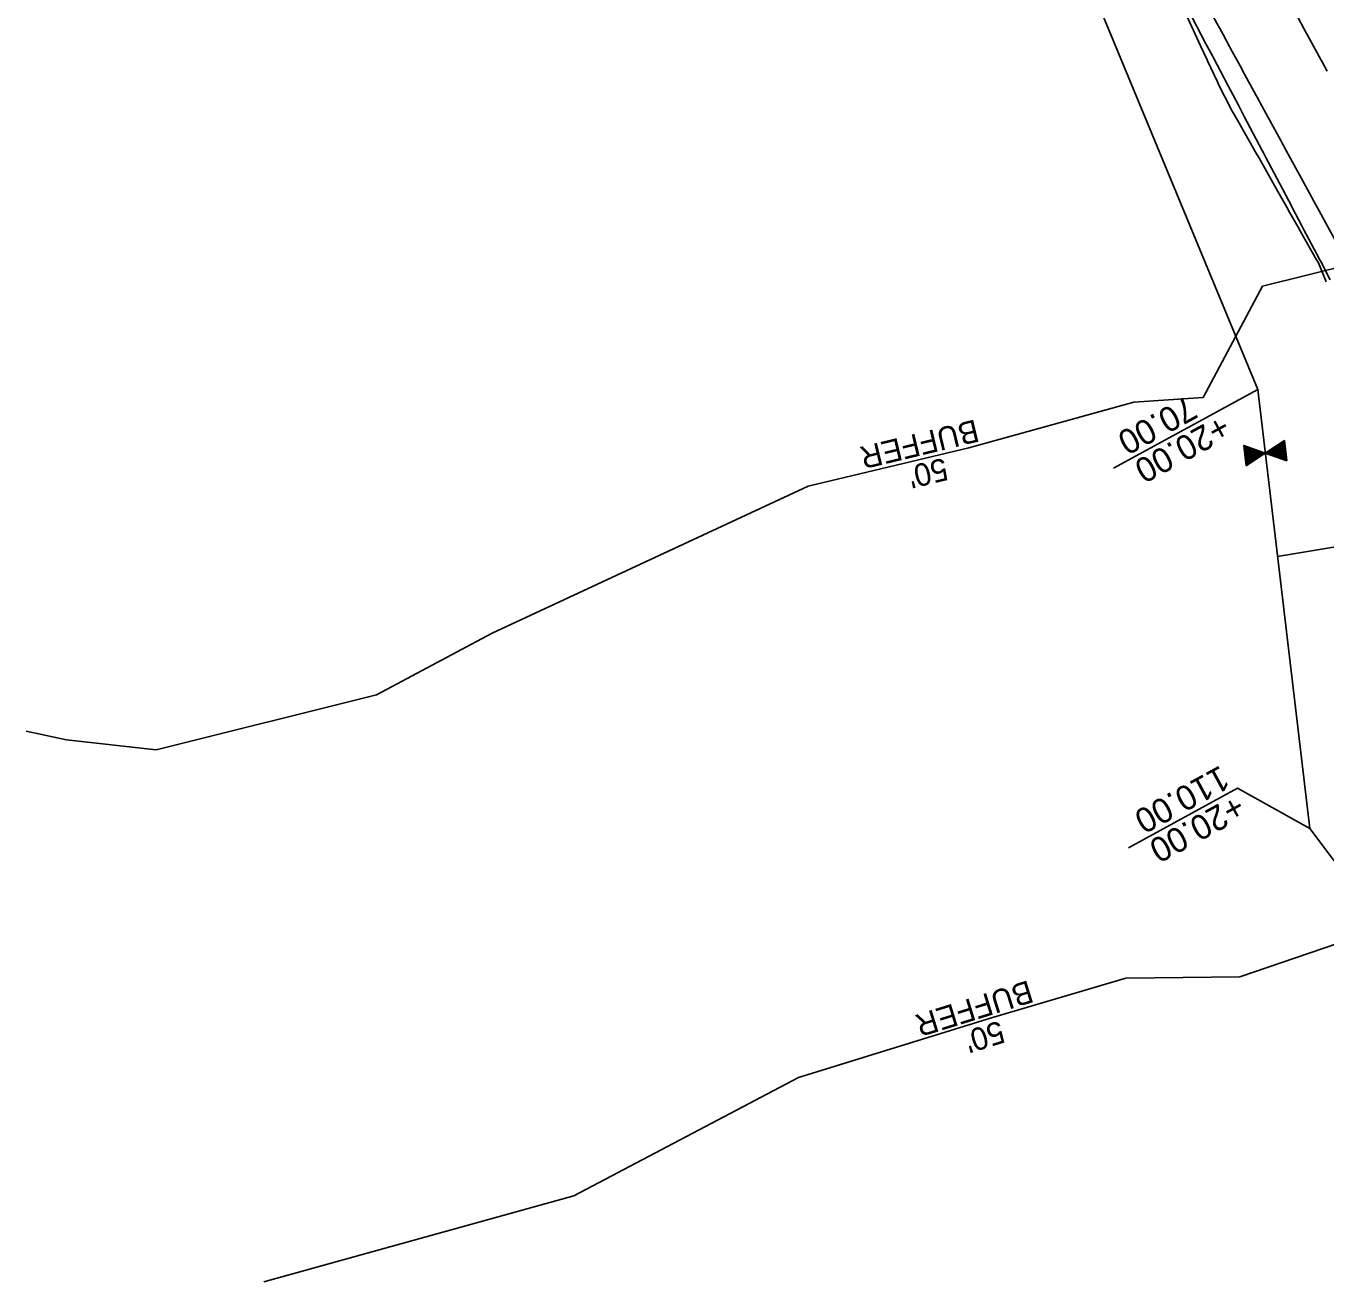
# Model space of a CAD drawing. Extents: x 1627557 to 1636561, y 783843 to 794002.
# Drawn here: x 1627658.9 to 1627975.8, y 784734.6 to 785040.7 of the extents above; entities that cross this region are included whole.
import ezdxf

# ---------------------------------------------------------------- set-up
doc = ezdxf.new("R2010")
doc.units = 0
for name, color, linetype in [('25 FT Buffer', 7, 'Continuous'), ('GATE', 7, 'Continuous'), ('R_Clearzone', 7, 'Continuous'), ('R_Ditch', 7, 'Continuous'), ('R_Proposed Const Limits', 7, 'Continuous'), ('R_Proposed Shoulder', 7, 'Continuous'), ('R_ROW', 7, 'Continuous'), ('R_ROW Annot', 7, 'Continuous')]:
    doc.layers.add(name, color=color, linetype=linetype)

msp = doc.modelspace()

# ---------------------------------------------------------------- linework, layer by layer
at = {"layer": '25 FT Buffer'}
for points in [[(1628054.55, 785023.15), (1628004.24, 784988.22), (1627960.38, 784977.27), (1627945.89, 784950.14), (1627929.03, 784949.04), (1627888.77, 784937.95), (1627849.63, 784928.54), (1627772.56, 784892.79), (1627744.38, 784877.73), (1627690.67, 784864.34), (1627668.83, 784866.74), (1627658.94, 784868.89)], [(1628128.73, 784912.02), (1628047.84, 784832.47), (1628028.94, 784828.64), (1627988.66, 784820.54), (1627954.84, 784809.03), (1627927.06, 784808.64), (1627894.29, 784799.05), (1627847.27, 784784.48), (1627792.52, 784755.67), (1627716.91, 784734.64)]]:
    msp.add_lwpolyline(points, dxfattribs=at)
at = {"layer": 'GATE'}
for p, q in [((1627965.69, 784934.93), (1627965.16, 784939.33)), ((1627965.79, 784934.89), (1627965.26, 784939.39)), ((1627965.9, 784934.86), (1627965.35, 784939.45)), ((1627966, 784934.82), (1627965.44, 784939.51)), ((1627966.11, 784934.78), (1627965.54, 784939.57)), ((1627966.21, 784934.74), (1627965.63, 784939.64)), ((1627956.37, 784933.54), (1627955.78, 784938.49)), ((1627956.47, 784933.6), (1627955.89, 784938.45)), ((1627956.56, 784933.66), (1627955.99, 784938.41)), ((1627956.65, 784933.72), (1627956.1, 784938.38)), ((1627956.75, 784933.79), (1627956.2, 784938.34)), ((1627956.84, 784933.85), (1627956.31, 784938.3)), ((1627956.93, 784933.91), (1627956.41, 784938.26)), ((1627957.03, 784933.97), (1627956.52, 784938.23)), ((1627957.12, 784934.03), (1627956.62, 784938.19)), ((1627957.21, 784934.09), (1627956.73, 784938.15)), ((1627957.31, 784934.15), (1627956.83, 784938.11)), ((1627957.4, 784934.22), (1627956.94, 784938.07)), ((1627957.49, 784934.28), (1627957.04, 784938.04)), ((1627957.59, 784934.34), (1627957.15, 784938)), ((1627957.68, 784934.4), (1627957.25, 784937.96)), ((1627957.77, 784934.46), (1627957.36, 784937.92)), ((1627957.87, 784934.52), (1627957.47, 784937.89)), ((1627957.96, 784934.58), (1627957.57, 784937.85)), ((1627958.05, 784934.65), (1627957.68, 784937.81)), ((1627958.15, 784934.71), (1627957.78, 784937.77)), ((1627958.24, 784934.77), (1627957.89, 784937.73)), ((1627958.33, 784934.83), (1627957.99, 784937.7)), ((1627958.43, 784934.89), (1627958.1, 784937.66)), ((1627958.52, 784934.95), (1627958.2, 784937.62)), ((1627958.61, 784935.01), (1627958.31, 784937.58)), ((1627958.71, 784935.08), (1627958.41, 784937.54)), ((1627958.8, 784935.14), (1627958.52, 784937.51)), ((1627958.89, 784935.2), (1627958.62, 784937.47)), ((1627958.99, 784935.26), (1627958.73, 784937.43)), ((1627959.08, 784935.32), (1627958.83, 784937.39)), ((1627959.17, 784935.38), (1627958.94, 784937.36)), ((1627959.27, 784935.45), (1627959.04, 784937.32)), ((1627959.36, 784935.51), (1627959.15, 784937.28)), ((1627959.45, 784935.57), (1627959.25, 784937.24)), ((1627959.55, 784935.63), (1627959.36, 784937.2)), ((1627959.64, 784935.69), (1627959.46, 784937.17)), ((1627959.73, 784935.75), (1627959.57, 784937.13)), ((1627959.83, 784935.81), (1627959.67, 784937.09)), ((1627959.92, 784935.88), (1627959.78, 784937.05)), ((1627960.01, 784935.94), (1627959.89, 784937.02)), ((1627960.11, 784936), (1627959.99, 784936.98)), ((1627960.2, 784936.06), (1627960.1, 784936.94)), ((1627960.29, 784936.12), (1627960.2, 784936.9)), ((1627960.39, 784936.18), (1627960.31, 784936.86)), ((1627960.48, 784936.24), (1627960.41, 784936.83)), ((1627960.57, 784936.31), (1627960.52, 784936.79)), ((1627960.67, 784936.37), (1627960.62, 784936.75)), ((1627960.76, 784936.43), (1627960.73, 784936.71)), ((1627960.85, 784936.49), (1627960.83, 784936.68)), ((1627960.95, 784936.55), (1627960.94, 784936.64)), ((1627961.06, 784936.59), (1627961.05, 784936.62)), ((1627961.16, 784936.56), (1627961.15, 784936.68)), ((1627961.27, 784936.52), (1627961.24, 784936.75)), ((1627961.37, 784936.48), (1627961.33, 784936.81)), ((1627961.48, 784936.44), (1627961.43, 784936.87)), ((1627961.58, 784936.41), (1627961.52, 784936.93)), ((1627961.69, 784936.37), (1627961.61, 784936.99)), ((1627961.79, 784936.33), (1627961.71, 784937.05)), ((1627961.9, 784936.29), (1627961.8, 784937.11)), ((1627962, 784936.25), (1627961.89, 784937.18)), ((1627962.11, 784936.22), (1627961.99, 784937.24)), ((1627962.22, 784936.18), (1627962.08, 784937.3)), ((1627962.32, 784936.14), (1627962.18, 784937.36)), ((1627962.43, 784936.1), (1627962.27, 784937.42)), ((1627962.53, 784936.07), (1627962.36, 784937.48)), ((1627962.64, 784936.03), (1627962.46, 784937.55)), ((1627962.74, 784935.99), (1627962.55, 784937.61)), ((1627962.85, 784935.95), (1627962.64, 784937.67)), ((1627962.95, 784935.91), (1627962.74, 784937.73)), ((1627963.06, 784935.88), (1627962.83, 784937.79)), ((1627963.16, 784935.84), (1627962.92, 784937.85)), ((1627963.27, 784935.8), (1627963.02, 784937.91)), ((1627963.37, 784935.76), (1627963.11, 784937.98)), ((1627963.48, 784935.72), (1627963.2, 784938.04)), ((1627963.58, 784935.69), (1627963.3, 784938.1)), ((1627963.69, 784935.65), (1627963.39, 784938.16)), ((1627963.79, 784935.61), (1627963.48, 784938.22)), ((1627963.9, 784935.57), (1627963.58, 784938.28)), ((1627964, 784935.54), (1627963.67, 784938.34)), ((1627964.11, 784935.5), (1627963.76, 784938.41)), ((1627964.21, 784935.46), (1627963.86, 784938.47)), ((1627964.32, 784935.42), (1627963.95, 784938.53)), ((1627964.42, 784935.38), (1627964.04, 784938.59)), ((1627964.53, 784935.35), (1627964.14, 784938.65)), ((1627964.64, 784935.31), (1627964.23, 784938.71)), ((1627964.74, 784935.27), (1627964.32, 784938.77)), ((1627964.85, 784935.23), (1627964.42, 784938.84)), ((1627964.95, 784935.2), (1627964.51, 784938.9)), ((1627965.06, 784935.16), (1627964.6, 784938.96)), ((1627965.16, 784935.12), (1627964.7, 784939.02)), ((1627965.27, 784935.08), (1627964.79, 784939.08)), ((1627965.37, 784935.04), (1627964.88, 784939.14)), ((1627965.48, 784935.01), (1627964.98, 784939.21)), ((1627965.58, 784934.97), (1627965.07, 784939.27)), ((1627994.48, 784916.47), (1627964.03, 784911.45))]:
    msp.add_line(p, q, dxfattribs=at)
for points in [[(1627966.29, 784934.71), (1627961.03, 784936.61), (1627965.7, 784939.68)], [(1627956.36, 784933.53), (1627961.03, 784936.61), (1627955.77, 784938.5)]]:
    msp.add_lwpolyline(points, close=True, dxfattribs=at)
at = {"layer": 'R_Clearzone'}
msp.add_lwpolyline([(1627979.03, 784986.75), (1627975.25, 784993.68), (1627974.67, 784994.75), (1627972.41, 784998.88), (1627972.3, 784999.09), (1627969.88, 785003.53), (1627965.75, 785011.1), (1627965.57, 785011.44), (1627965.09, 785012.31), (1627964.83, 785012.79), (1627960.31, 785021.09), (1627959.09, 785023.33), (1627958.84, 785023.78), (1627955.52, 785029.87), (1627955.28, 785030.31), (1627952.58, 785035.26), (1627952.34, 785035.69), (1627950.73, 785038.65), (1627946.07, 785047.2)], dxfattribs=at)
at = {"layer": 'R_Ditch'}
msp.add_lwpolyline([(1627976.88, 784978.87), (1627974.55, 784983.29), (1627974.18, 784983.99), (1627974.13, 784984.08), (1627970.45, 784991.07), (1627969.89, 784992.14), (1627967.69, 784996.31), (1627967.58, 784996.52), (1627965.23, 785000.99), (1627961.21, 785008.63), (1627961.03, 785008.96), (1627960.57, 785009.84), (1627960.31, 785010.33), (1627955.9, 785018.69), (1627954.72, 785020.94), (1627954.47, 785021.4), (1627951.24, 785027.54), (1627951.01, 785027.98), (1627948.38, 785032.97), (1627948.15, 785033.41), (1627946.58, 785036.39), (1627942.05, 785045)], dxfattribs=at)
at = {"layer": 'R_Proposed Const Limits'}
msp.add_lwpolyline([(1627975.91, 784978.34), (1627973.98, 784982.99), (1627973.59, 784983.67), (1627973.54, 784983.76), (1627969.63, 784990.62), (1627969.03, 784991.68), (1627966.7, 784995.77), (1627966.58, 784995.98), (1627964.1, 785000.38), (1627959.88, 785007.91), (1627959.7, 785008.24), (1627959.2, 785009.1), (1627958.93, 785009.58), (1627954.23, 785017.78), (1627952.97, 785019.99), (1627952.71, 785020.44), (1627949.58, 785026.63), (1627949.37, 785027.08), (1627946.98, 785032.21), (1627946.77, 785032.66), (1627945.35, 785035.71), (1627941.23, 785044.56)], dxfattribs=at)
at = {"layer": 'R_Proposed Shoulder'}
msp.add_lwpolyline([(1627976.11, 785029.71), (1627974.89, 785031.94), (1627974.64, 785032.4), (1627971.32, 785038.49), (1627971.08, 785038.92), (1627968.38, 785043.88)], dxfattribs=at)
at = {"layer": 'R_ROW'}
for p, q in [((1627959.18, 784952.13), (1627851.48, 785212.33)), ((1627971.93, 784845.19), (1627959.18, 784952.13)), ((1628014.22, 784788.52), (1627971.93, 784845.19))]:
    msp.add_line(p, q, dxfattribs=at)
at = {"layer": 'R_ROW Annot'}
for points in [[(1627959.18, 784952.13), (1627924.06, 784932.99)], [(1627971.93, 784845.19), (1627954.29, 784854.97), (1627927.66, 784840.45)]]:
    msp.add_lwpolyline(points, dxfattribs=at)

# ---------------------------------------------------------------- texts
at = {"layer": '25 FT Buffer'}
for s, rotation, p in [('BUFFER', 193.5107, (1627890.4, 784944.89)), ("50'", 193.5107, (1627882.84, 784935.53)), ('BUFFER', 197.2073, (1627903.33, 784808.24)), ("50'", 197.2073, (1627896.39, 784798.41))]:
    msp.add_text(s, height=5.5, rotation=rotation, dxfattribs=at).set_placement(p)
at = {"layer": 'R_ROW Annot'}
for s, p in [('70.00', (1627942.14, 784950.82)), ('+20.00', (1627950.36, 784946.19)), ('110.00', (1627950.13, 784860.68)), ('+20.00', (1627953.96, 784853.65))]:
    msp.add_text(s, height=6, rotation=208.601, dxfattribs=at).set_placement(p)

doc.saveas('drawing.dxf')
